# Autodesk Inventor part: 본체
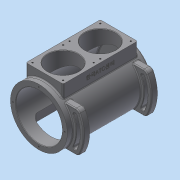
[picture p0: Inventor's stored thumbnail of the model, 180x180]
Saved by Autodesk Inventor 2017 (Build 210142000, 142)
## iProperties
Created: 2016-11
Part Number: 본체
Material: 알루미늄 6061
Document SubType Name: Modeling
Designer: mduedu
Density: 2.71 g/cm^3
Mass: 2446.31 g
Surface Area: 1767.27 cm^2
Volume: 902.698 cm^3
Appearance: 기본값
Author: mduedu
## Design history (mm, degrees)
sketch "스케치1"
  geometry: C1 r 65 at (0, 0); 1 further point
  constraints: 1 centre point, 1 coincident
  dimensions: "d119" = 130 diameter of C1
extrude "돌출1" new body sketch "스케치1" distance "d3" = 98; taper "d4" = 0 deg; dims "d132" = 97, "d133" = 0
feature "쉘1" dims "d120" = 12, "d134" = 8
node "작업 평면2"
sketch "스케치13"
  geometry: L1 (42.5, 85)-(-42.5, 85); L2 (-42.5, 85)-(-42.5, -85); L3 (-42.5, -85)-(42.5, -85); L4 (42.5, -85)-(42.5, 85); 2 further points
  constraints: 8 end point, 2 parallel, 1 horizontal, 1 midpoint, 1 perpendicular, 1 vertical alignment
  dimensions: "d122" = 170 distance of L1.end L2.end; "d124" = 85 distance of L2.end L3.end; "d125" = 85 distance from line of point (0, 0) L1 (= 0.5 x d122)
extrude "돌출11" join sketch "스케치13" stored distance "d126" = 10; taper "d127" = 0 deg
sketch "스케치14"
  geometry: L1 (65, 97)-(-65, 97) reference; C1 r 35 at (0, 42.5); 1 further point
  constraints: 1 centre point, 1 vertical alignment
  dimensions: "d128" = 70 diameter of C1; "d129" = 54.5 distance from line of C1.centre L1
extrude "돌출12" cut sketch "스케치14" stored distance "d130" = 10; taper "d131" = 0 deg
sketch "스케치15"
  geometry: C1 r 53 at (0, 0) reference; 1 further point
extrude "돌출13" cut sketch "스케치15" stored distance "d135" = 10; taper "d136" = 0 deg
chamfer "모따기1" distance "d54" = 1; stored, may be unused: second distance "d55" = 2, angle "d56" = 45 deg
sketch "스케치8"
  geometry: C1 r 30 at (0, 0); C2 r 65 at (0, 0) reference; 1 further point
  constraints: 1 centre point, 1 concentric
  dimensions: "d57" = 60 diameter of C1
extrude "돌출8" join sketch "스케치8" distance "d58" = 14; taper "d59" = 0 deg
hole "구멍3" diameter "d62" = 41; stored, may be unused: countersink angle "d66" = 90 deg, drill point angle "d68" = 0 deg; dims "d63" = 6, "d64" = 47, "d65" = 14, "d67" = 17, "d195" = 10, "d196" = 10
fillet "모깎기11" dims "d69" = 3
fillet "모깎기12" dims "d70" = 3
fillet "모깎기13" dims "d71" = 0.3
chamfer "모따기2" distance "d72" = 1; stored, may be unused: second distance "d73" = 2, angle "d74" = 45 deg
node "작업 평면3"
sketch "스케치16"
  geometry: L1 (-42.5, -80)-(47.5, -80); L2 (-42.5, -80)-(21.14, -16.36); L3 (-42.5, -80)-(21.14, -143.64); L4 (3.462, -34.038)-(34.879, -34.038); L5 (3.462, -125.962)-(34.879, -125.962); A1 r 65 centre (-42.5, -80) between (3.462, -34.038) and (3.462, -125.962) reference; A2 r 90 centre (-42.5, -80) between (34.879, -125.962) and (34.879, -34.038); A3 r 90 centre (-42.5, -80) between (34.879, -34.038) and (34.879, -125.962); A4 r 65 centre (-42.5, -80) between (3.462, -125.962) and (3.462, -34.038); 1 further point
  constraints: 11 point on circle, 10 end point, 3 centre point, 2 parallel, 2 point on line, 1 coincident, 1 horizontal
  dimensions: "d140" = 45 deg angle of L3 L1; "d141" = 45 deg angle of L2 L1; "d142" = 25 radial gap between concentric circles of A1 A2
extrude "돌출14" join sketch "스케치16" distance "d143" = 15; taper "d144" = 0 deg
sketch "스케치17"
  geometry: L1 (-42.5, -80)-(34.414, -80); L2 (-42.5, -80)-(27.208, -47.495); L3 (-42.5, -80)-(27.208, -112.505); L4 (34.879, -34.038)-(3.462, -34.038) reference; L5 (3.462, -125.962)-(34.879, -125.962) reference; A1 r 65 centre (-42.5, -80) between (3.462, -34.038) and (3.462, -125.962) reference; A2 r 76.914 centre (-42.5, -80) between (19.17, -125.962) and (19.17, -34.038); A3 r 4 centre (27.208, -47.495) between (23.582, -49.185) and (30.833, -45.804); A4 r 4 centre (27.208, -112.505) between (30.833, -114.196) and (23.582, -110.815); A5 r 80.914 centre (-42.5, -80) between (30.833, -114.196) and (30.833, -45.804); A6 r 72.914 centre (-42.5, -80) between (23.582, -110.815) and (23.582, -49.185); 1 further point
  constraints: 13 point on circle, 6 end point, 5 centre point, 5 coincident, 3 midpoint, 2 point on line, 1 equal radius, 1 horizontal
  dimensions: "d145" = 25 deg angle of L1 L3; "d146" = 25 deg angle of L2 L1; "d147" = 8 diameter of A3
extrude "돌출15" cut sketch "스케치17" stored distance "d150" = 15; taper "d151" = 0 deg
fillet "모깎기17" dims "d152" = 10
fillet "모깎기18" dims "d153" = 2
fillet "모깎기19" dims "d154" = 2
chamfer "모따기4" distance "d155" = 1; stored, may be unused: second distance "d156" = 2, angle "d157" = 45 deg
fillet "모깎기20" dims "d159" = 3
fillet "모깎기21" dims "d160" = 3
fillet "모깎기22" dims "d161" = 3
node "작업 평면4"
sketch "스케치18"
  geometry: L1 (-42.5, 70)-(42.5, 70); L2 (42.5, 70)-(42.5, -70); L3 (42.5, -70)-(-42.5, -70); L4 (-42.5, -70)-(-42.5, 70); 2 further points
  constraints: 8 end point, 2 parallel, 1 horizontal, 1 midpoint, 1 perpendicular, 1 vertical alignment
  dimensions: "d162" = 140 distance of L1.end L2.end; "d164" = 85 distance of L2.end L3.end; "d165" = 70 distance from line of point (0, 0) L1 (= 0.5 x d162)
extrude "돌출16" cut sketch "스케치18" stored distance "d166" = 15; taper "d167" = 0 deg
fillet "모깎기23" dims "d168" = 10
fillet "모깎기24" dims "d173" = 3
sketch "스케치19"
  geometry: 4 further points
  constraints: 4 other
hole "구멍6" sketch "스케치19" at (0, -59), (59, 0), (-59, 0), (0, 59) diameter "d174" = 3.242; stored, may be unused: countersink angle "d178" = 90 deg, drill point angle "d180" = 120 deg; dims "d175" = 8, "d176" = 4, "d177" = 2, "d179" = 10
sketch "스케치20"
  geometry: L1 (35, -77.5)-(-35, -77.5); L2 (-35, -77.5)-(-35, -7.5); L3 (-35, -7.5)-(35, -7.5); L4 (35, -7.5)-(35, -77.5); L5 (35, -77.5)-(-35, -7.5); L6 (-35, -77.5)-(35, -7.5); C1 r 36 at (0, -42.5) reference; 5 further points
  constraints: 12 end point, 4 coincident, 2 midpoint, 2 parallel, 1 horizontal, 1 perpendicular
  dimensions: "d181" = 70 distance of L2.end L3.end; "d182" = 70 distance of L1.end L2.end
hole "구멍7" sketch "스케치20" at (-35, -77.5), (-35, -7.5), (35, -7.5), (35, -77.5) diameter "d183" = 3.242; stored, may be unused: countersink angle "d187" = 90 deg, drill point angle "d189" = 118 deg; dims "d184" = 8, "d185" = 4, "d186" = 2, "d188" = 10
sketch "스케치21"
  geometry: L1 (164, 0)-(0, 0) reference; L2 (-3, 0)-(-3, -24.649) reference; 3 further points
  constraints: 1 midpoint, 1 vertical alignment, 1 other
  dimensions: "d190" = 15 distance from line of point (82, -15) L1; "d191" = 85 distance from line of point (82, 0) L2 (derived)
feature "엠보싱2" sketch "스케치21" dims "d3" = 98, "d4" = 0, "d119" = 130, "d132" = 97, "d133" = 0, "d192" = 0.5, "d193" = 0
node "솔리드1"
mirror "대칭5"
mirror "대칭6"
mirror "대칭7"
